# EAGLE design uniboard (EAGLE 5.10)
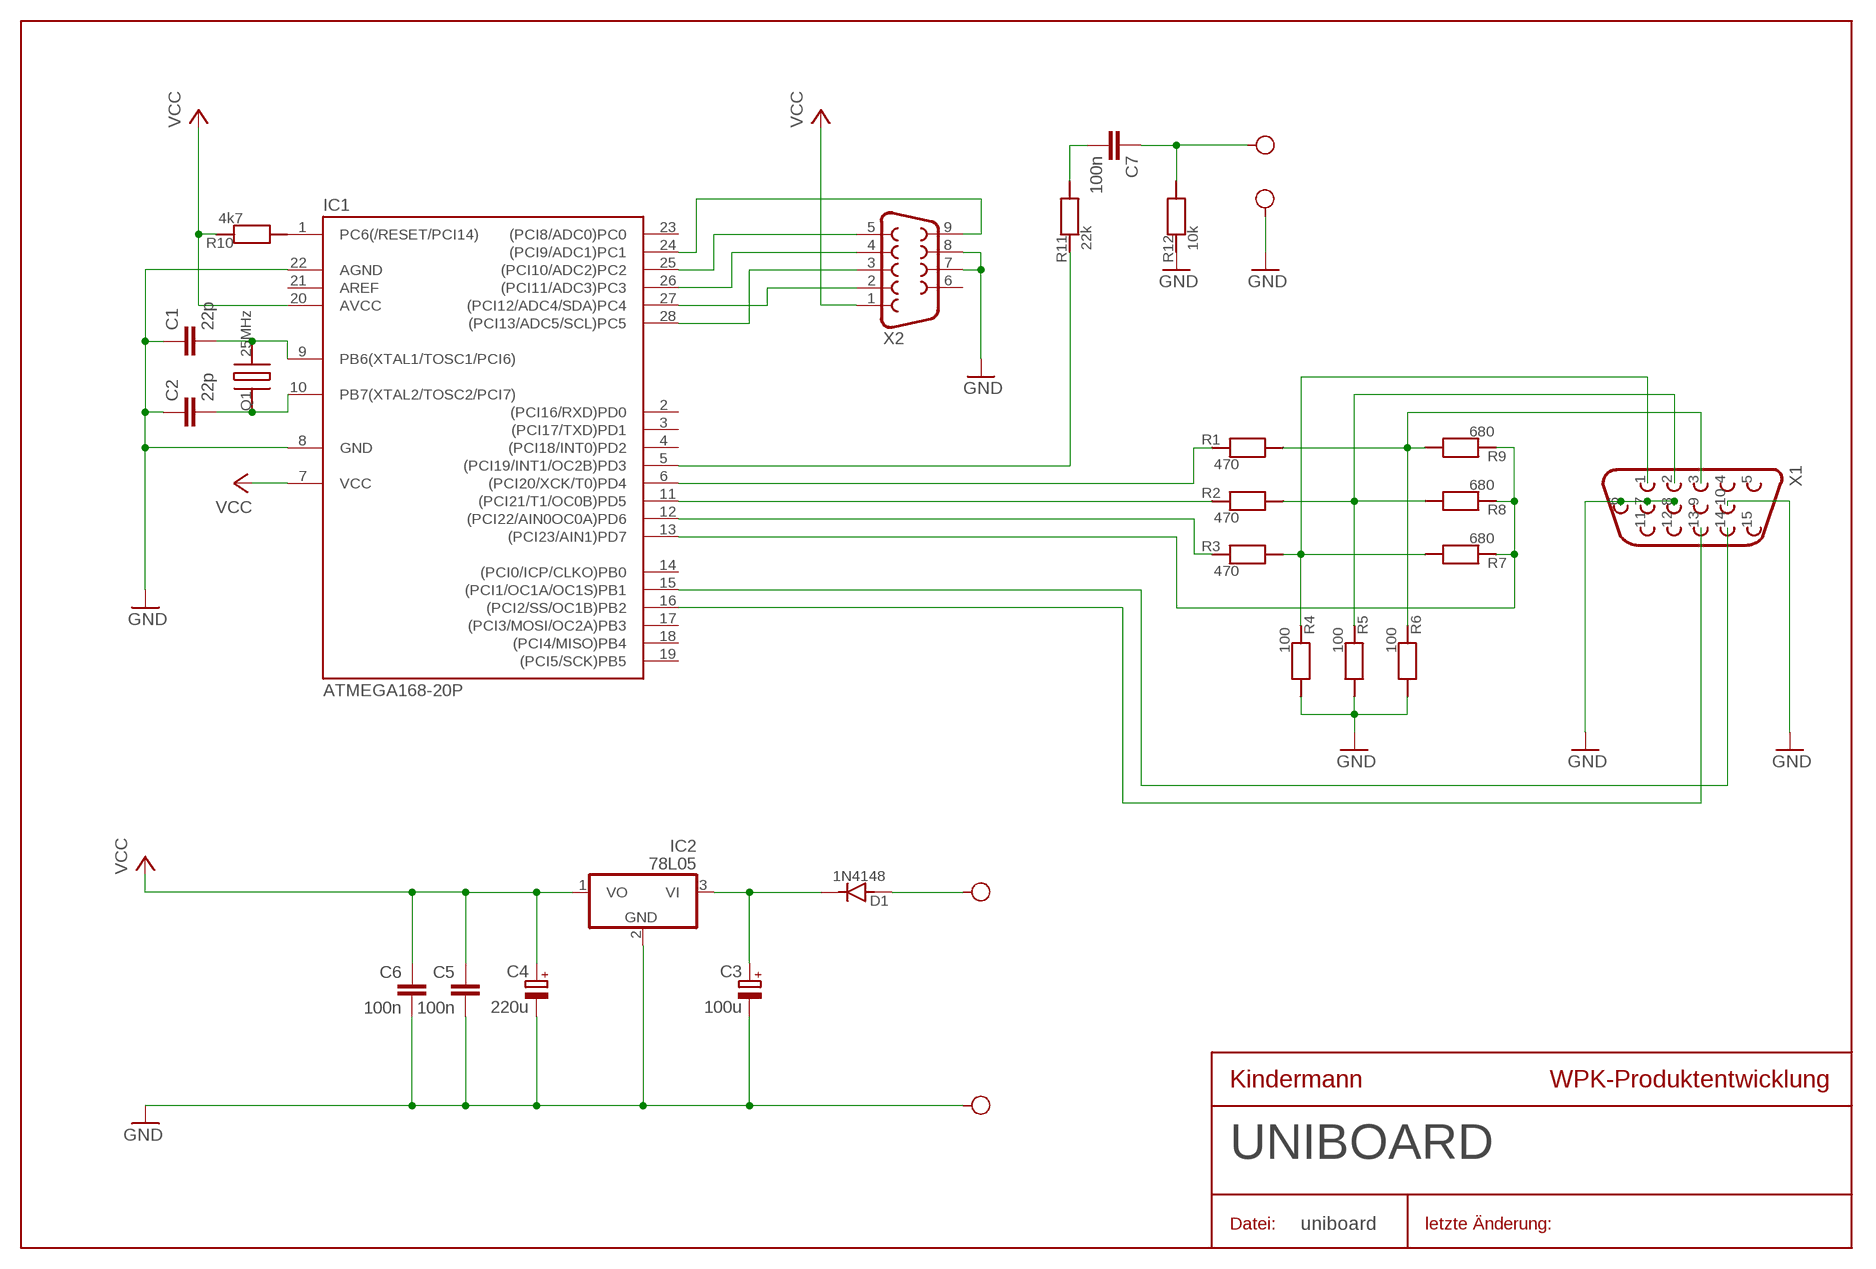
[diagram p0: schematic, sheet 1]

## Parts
C1  22p  KERKO-5.0  [KERKO-5.0]
C2  22p  KERKO-5.0  [KERKO-5.0]
C3  100u  ELKO-GR  [ELKO-GR-5.0]
C4  220u  ELKO-KL  [ELKO-KL-5.0]
C5  100n  VS-KERKO-5.0  [VS-KERKO-5.0]
C6  100n  VS-KERKO-5.0  [VS-KERKO-5.0]
C7  100n  VS-KERKO-5.0  [VS-KERKO-5.0]
D1  1N4148  [DIO-7.5]
GND  GND  [LOETN]
IC1  ATMEGA168-20P  ATMEGA-168  [DIL28-3]
IC2  78L05  [TO92]
Q1  25MHz  QUARZ  [QUARZ]
R1  470  WID-470  [WID-470]
R2  470  WID-470  [WID-470]
R3  470  WID-470  [WID-470]
R4  100  WID-100  [WID-100]
R5  100  WID-100  [WID-100]
R6  100  WID-100  [WID-100]
R7  680  WID-680  [WID-680]
R8  680  WID-680  [WID-680]
R9  680  WID-680  [WID-680]
R10  4k7  WID-4.7K  [WID-4.7K]
R11  22k  WID-22K  [WID-22K]
R12  10k  WID-10K  [WID-10K]
U$1  GND  [LOETN]
U$4  AUDIO  [LOETN]
VCC  VCC  [LOETN]
X1  VGA-BU-15POL  [VGA-BU-15POL]
X2  D-SUB-ST-9POL  [M09HP]

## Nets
B: R1.P2 R6.P1 R9.P2 X1.3
G: R2.P2 R5.P1 R8.P2 X1.2
GND: C1.1 C2.1 C3.- C4.- C5.2 C6.2 GND.PIN IC1.8(GND) IC1.22(AGND) IC2.2(GND) R4.P2 R5.P2 R6.P2 R12.1 U$1.PIN X1.6 X1.7 X1.8 X1.10 X2.7 X2.8
H/C-SYNC: IC1.16((PCI2/SS/OC1B)PB2) X1.13
N$1: C1.2 IC1.9(PB6(XTAL1/TOSC1/PCI6)) Q1.2
N$2: C7.1 R12.2 U$4.PIN
N$3: C2.2 IC1.10(PB7(XTAL2/TOSC2/PCI7)) Q1.1
N$4: IC1.11((PCI21/T1/OC0B)PD5) R2.P1
N$5: IC1.6((PCI20/XCK/T0)PD4) R1.P1
N$6: IC1.12((PCI22/AIN0OC0A)PD6) R3.P1
N$7: IC1.13((PCI23/AIN1)PD7) R7.P1 R8.P1 R9.P1
N$8: IC1.27((PCI12/ADC4/SDA)PC4) X2.2
N$12: IC1.24((PCI9/ADC1)PC1) X2.9
N$14: C7.2 R11.P2
N$17: IC1.5((PCI19/INT1/OC2B)PD3) R11.P1
N$21: IC1.28((PCI13/ADC5/SCL)PC5) X2.3
N$22: IC1.26((PCI11/ADC3)PC3) X2.4
N$27: IC1.25((PCI10/ADC2)PC2) X2.5
PIN: D1.A VCC.PIN
R: R3.P2 R4.P1 R7.P2 X1.1
RESET: IC1.1(PC6(/RESET/PCI14)) R10.P2
VCC: C4.+ C5.1 C6.1 IC1.7(VCC) IC1.20(AVCC) IC2.1(VO) R10.P1 X2.1
VIN3: C3.+ D1.K IC2.3(VI)
VSYNC: IC1.15((PCI1/OC1A/OC1S)PB1) X1.14
Unconnected: IC1.2((PCI16/RXD)PD0) IC1.3((PCI17/TXD)PD1) IC1.4((PCI18/INT0)PD2) IC1.14((PCI0/ICP/CLKO)PB0) IC1.17((PCI3/MOSI/OC2A)PB3) IC1.18((PCI4/MISO)PB4) IC1.19((PCI5/SCK)PB5) IC1.21(AREF) IC1.23((PCI8/ADC0)PC0) X1.4 X1.5 X1.9 X1.11 X1.12 X1.15 X2.6

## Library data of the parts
C1 C2 = pacman:KERKO-5.0: Keramik-Kondensator
C3 = pacman:ELKO-GR: Elektrolytkondensator, 10x12,5mm, RM 5,0mm
C4 = pacman:ELKO-KL: Elektrolytkondensator, 5x12,5mm, RM 5,0mm
C5-C7 = pacman:VS-KERKO-5.0: Vielschicht-Keramikkondensator
D1 = pacman:1N4148
GND U$1 = pacman:GND
IC1 = pacman:ATMEGA-168: Atmel AVR-RISC-Controller
IC2 = uniboard:78L05: Spannungsregler 0,1A positiv
Q1 = pacman:QUARZ: Quarz
R1-R3 = pacman:WID-470: Widertsand 470 Ohm
R4-R6 = pacman:WID-100: Widerstand 100 Ohm
R7-R9 = pacman:WID-680: Widerstand 680 Ohm
R10 = pacman:WID-4.7K: Widerstand 4.7K Ohm
R11 = pacman:WID-22K: Widerstand 22K Ohm
R12 = pacman:WID-10K: Widerstand 10K-Ohm
U$4 = pacman:AUDIO
VCC = pacman:VCC
X1 = uniboard:VGA-BU-15POL: VGA-Buchse 15pol
X2 = pacman:D-SUB-ST-9POL: D-SUB-Stecker, 9-polig, gewinkelt, RM 9,4

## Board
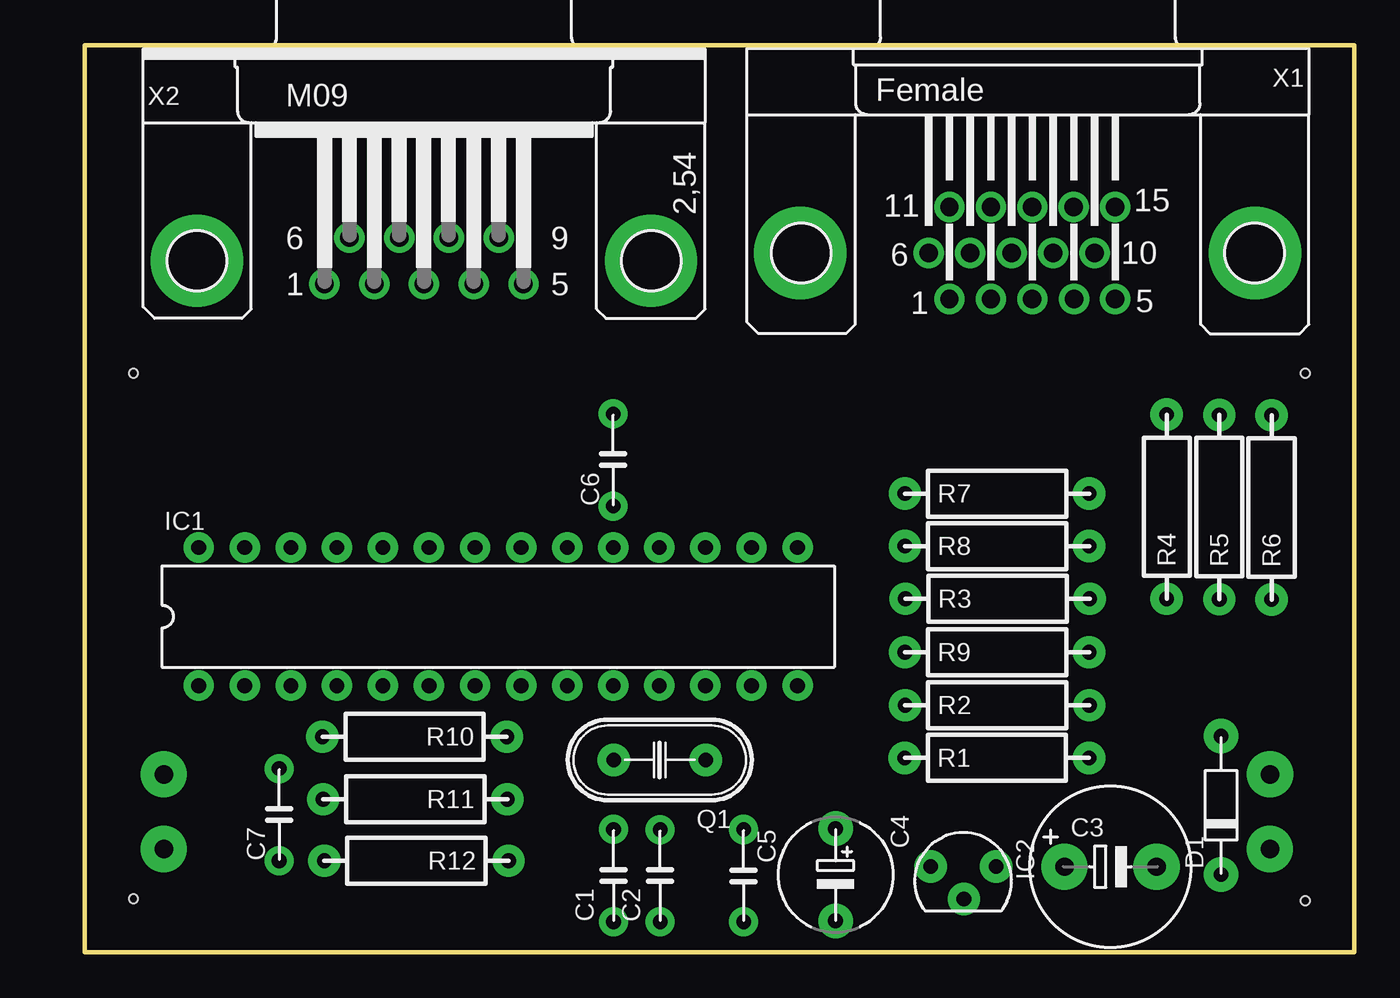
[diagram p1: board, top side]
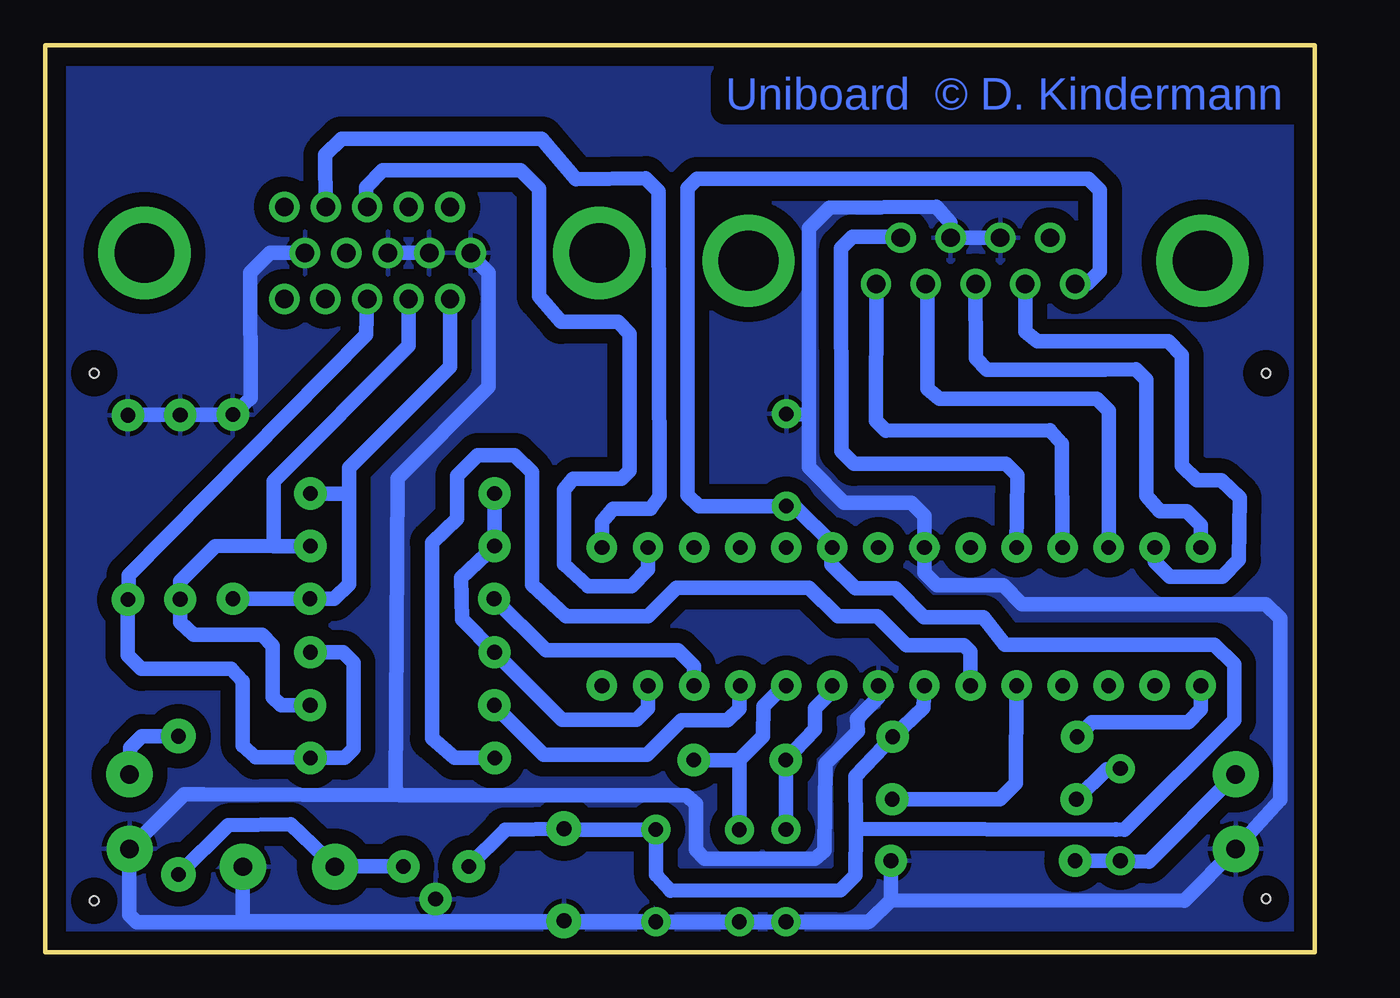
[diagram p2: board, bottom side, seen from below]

Size 70 x 50 mm. Coordinates in mm from the lower left corner, seen from the top.
Outline: 0,0 0,50 70,50 70,0 0,0
Copper layers (1*16): Top 0.035mm / dielectric 1.5mm / Bottom 0.035mm
Design rules "default": minimum track width 10mil, minimum drill 24mil, track to track 8mil, track to pad 8mil, pad to pad 8mil, via to via 8mil, smd to smd 8mil, copper to edge 40mil, drill to drill 8mil, minimum pad ring 10mil, minimum via ring 8mil, stop-mask expansion 4mil, vias tented up to drill 0mil, thermal gap 10mil
Holes 0.5 mm at 2.69,31.93 2.69,2.96 67.3,31.93 67.3,2.85

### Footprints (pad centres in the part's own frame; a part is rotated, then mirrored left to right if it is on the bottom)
KERKO-5.0 = drill 0.813 pad 1.6 round: 1 -2.54,0; 2 2.54,0
ELKO-GR-5.0 = drill 1.016 pad 2.54 round: + -2.54,0; - 2.54,0
ELKO-KL-5.0 = drill 0.813 pad 1.905 round: + -2.54,0; - 2.54,0
VS-KERKO-5.0 = drill 0.813 pad 1.6 round: 1 -2.54,0; 2 2.54,0
DIO-7.5 = drill 0.813 pad 1.905 round: A 3.81,0; K -3.81,0
LOETN = drill 1.016 pad 2.54 round: PIN 0,0
DIL28-3 = drill 0.813 pad 1.676 round: 1 -16.51,-3.81; 2 -13.97,-3.81; 3 -11.43,-3.81; 4 -8.89,-3.81; 5 -6.35,-3.81; 6 -3.81,-3.81; 7 -1.27,-3.81; 8 1.27,-3.81; 9 3.81,-3.81; 10 6.35,-3.81; 11 8.89,-3.81; 12 11.43,-3.81; 13 13.97,-3.81; 14 16.51,-3.81; 15 16.51,3.81; 16 13.97,3.81; 17 11.43,3.81; 18 8.89,3.81; 19 6.35,3.81; 20 3.81,3.81; 21 1.27,3.81; 22 -1.27,3.81; 23 -3.81,3.81; 24 -6.35,3.81; 25 -8.89,3.81; 26 -11.43,3.81; 27 -13.97,3.81; 28 -16.51,3.81
TO92 = drill 0.813 pad 1.778 round: 1 0,-1.795; 2 1.794,0.035; 3 0,1.812
QUARZ = drill 0.813 pad 1.778 round: 1 0,0; 2 5.08,0
WID-470 = drill 0.813 pad 1.778 round: P1 -5.08,0; P2 5.08,0
WID-100 = drill 0.813 pad 1.778 round: P1 -5.08,0; P2 5.08,0
WID-680 = drill 0.813 pad 1.778 round: P1 -5.08,0; P2 5.08,0
WID-4.7K = drill 0.813 pad 1.778 round: P1 -5.08,0; P2 5.08,0
WID-22K = drill 0.813 pad 1.778 round: P1 -5.08,0; P2 5.08,0
WID-10K = drill 0.813 pad 1.778 round: 1 -5.08,0; 2 5.08,0
VGA-BU-15POL = drill 1.016 pad 1.676 round: 1 4.329,2.54; 2 2.043,2.54; 3 -0.243,2.54; 4 -2.54,2.529; 5 -4.815,2.54; 6 5.472,0; 7 3.186,0; 8 0.9,0; 9 -1.386,0; 10 -3.672,0; 11 4.329,-2.54; 12 2.043,-2.54; 13 -0.243,-2.54; 14 -2.529,-2.54; 15 -4.815,-2.54 | drill 3.302 pad 5.08 round: G1 -12.522,0; G3 12.56,0
M09HP = drill 1.016 pad 1.676 round: 1 -5.486,-1.27; 2 -2.743,-1.27; 3 0,-1.27; 4 2.743,-1.27; 5 5.486,-1.27; 6 -4.115,1.27; 7 -1.372,1.27; 8 1.372,1.27; 9 4.115,1.27 | drill 3.302 pad 5.08 round: G1 -12.522,0; G2 12.522,0

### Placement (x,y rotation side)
C1  29.16,4.24 90 top
C2  31.73,4.23 90 top
C3  56.56,4.72 0 top
C4  41.4,4.28 270 top
C5  36.34,4.24 270 top
C6  29.14,27.15 90 top
C7  10.72,7.6 90 top
D1  62.66,8.11 90 top
GND  65.36,5.7 90 top
IC1  22.8,18.51 0 top
IC2  48.45,4.74 270 top
Q1  34.25,10.61 180 top
R1  50.3,10.72 0 top
R2  50.32,13.63 0 top
R3  50.34,19.49 0 top
R4  59.66,24.57 90 top
R5  62.56,24.55 90 top
R6  65.44,24.53 90 top
R7  50.31,25.29 0 top
R8  50.31,22.4 0 top
R9  50.31,16.55 0 top
R10  18.19,11.89 180 top
R11  18.23,8.44 180 top
R12  18.29,5.05 180 top
U$1  4.36,5.7 270 top
U$4  4.36,9.81 270 top
VCC  65.36,9.81 90 top
X1  52.01,38.56 180 top
X2  18.71,38.13 0 top

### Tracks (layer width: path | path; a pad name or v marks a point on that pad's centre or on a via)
B
  Bottom 0.813: R9.P2 53.58,16.55 53.01,15.98 53.01,11.22 53.51,10.72 R1.P2 55.41,10.75 58.41,10.75 59.11,11.4 59.11,14.94 59.75,15.63 64.7,15.63 65.46,16.38 65.45,19.49 65.4,19.49 | X1.3 52.31,34.04 65.4,20.79 65.4,19.49 | 65.4,19.49 R6.P1
G
  Bottom 0.406: 57.41,22.41 57.4,22.4
  Bottom 0.813: R2.P2 57.01,13.63 57.45,14.07 57.45,16.92 58.04,17.51 61.82,17.51 62.56,18.21 R5.P1 62.56,20.45 60.64,22.39 57.41,22.41 57.4,24.25 57.4,25.99 49.97,33.43 X1.2 | 57.4,22.4 R8.P2
GND
  Bottom 0.406: R12.1 23.64,5.05 23.64,5.11 23.43,5.11 23.43,2.63 23.7,2.63 24.68,1.66 | GND.PIN
  Bottom 0.813: X2.7 X2.8 20.08,40.23 20.86,41.09 26.76,41.04 27.89,39.92 27.89,29.63 | IC1.8 24.07,14.07 25.24,12.89 25.19,12.19 26.98,10.39 27.03,5.61 27.57,5.16 33.64,5.16 34.13,5.65 34.13,8.21 34.67,8.65 50.47,8.65 | 50.47,8.65 61.29,8.71 62.35,8.71 GND.PIN | X1.6 46.54,38.44 45.56,37.46 45.56,31.18 50.58,26.14 50.68,8.99 50.47,8.65 | R6.P2 65.42,29.63 R5.P2 61.26,29.63 R4.P2 58.68,30.55 58.7,37.46 57.61,38.55 X1.10 | 27.89,29.63 C6.2 | 27.89,29.63 27.89,26.73 25.95,24.8 22.25,24.8 21.52,24.07 IC1.22 21.53,20.93 20.83,20.23 17.16,20.23 16.14,19.21 2.7,19.21 1.91,18.41 1.9,8.42 U$1.PIN 7.19,2.86 23.38,2.87 | 23.38,2.87 R12.1 | 23.38,2.87 24.59,1.69 C1.1 C2.1 36.33,1.69 C5.2 36.47,1.7 36.47,1.73 C4.- 48.47,1.73 48.45,1.72 | IC2.2 48.47,2.94 48.45,1.72 | C3.- 59.13,4.72 59.11,1.72 48.45,1.72 | 24.68,1.66 64.96,1.66 65.37,2.06 GND.PIN | X1.7 X1.8
  pour Bottom (isolate 0.813): 69.9,0.1 69.83,50.11 -0.04,49.96 -0.07,0
H/C-SYNC
  Bottom 0.813: IC1.16 36.77,21.11 37.68,20.19 40.07,20.19 41.38,21.4 41.38,25.52 40.89,26.1 38.23,26.12 37.77,26.56 37.77,34.11 38.42,34.75 41.57,34.75 42.78,36.17 42.78,42.09 43.8,43.11 51.39,43.11 52.32,42.18 52.32,41.16 X1.13
N$1
  Bottom 0.813: C1.2 29.16,8.07 Q1.2 29.11,10.66 28.18,11.66 27.55,12.29 27.55,13.46 26.56,14.45 26.56,14.66 IC1.9
N$2
  Bottom 0.813: R12.2 C7.1 9.16,5 U$4.PIN
N$3
  Bottom 0.813: IC1.10 29.26,14.7 30.39,13.58 30.44,11.91 31.76,10.59 | 31.76,10.59 33.73,10.59 Q1.1 | C2.2 31.73,10.56 31.76,10.59
N$4
  Bottom 0.813: R2.P1 45.24,13.61 42.53,10.9 36.82,10.9 34.91,12.8 32.37,12.8 31.74,13.44 31.74,14.65 IC1.11
N$5
  Bottom 0.813: R1.P1 47.43,10.72 48.68,11.8 48.68,22.59 47.3,23.92 47.3,26.27 46.16,27.41 44.12,27.41 43.17,26.46 43.15,20.27 41.28,18.52 36.77,18.52 35.18,20.11 27.88,20.11 26.29,18.52 24.12,18.52 22.53,16.93 19.36,16.93 18.99,16.57 IC1.6
N$6
  Bottom 0.813: R3.P1 42.4,16.65 35.11,16.64 34.24,15.78 IC1.12
N$7
  Bottom 0.813: R7.P1 R8.P1 47.07,20.64 47.02,18.36 R9.P1 41.51,12.82 37.4,12.82 36.77,13.45 IC1.13
N$8
  Bottom 0.813: X2.2 15.96,34.22 15.31,33.7 8.08,33.7 7.33,32.91 7.33,26.82 6.49,26.02 5.17,26.02 4.14,25.06 4.18,21.63 5.11,20.71 7.98,20.71 8.82,21.54 8.82,22.32 IC1.27
N$12
  Bottom 0.813: IC1.24 16.4,26.31 17.03,26.93 25.43,26.93 26.1,27.63 26.13,38.83 25.5,39.46 22.89,39.46 X2.9
N$14
  Bottom 0.813: R11.P2 11.47,10.11 C7.2
N$17
  Bottom 0.813: IC1.5 16.47,9.32 17.35,8.44 R11.P1
N$21
  Bottom 0.813: X2.3 18.7,32.76 18.09,32.13 11.58,32.13 9.87,32.15 9.28,31.56 9.28,25.16 8.54,24.32 7.06,24.32 6.29,23.55 IC1.28
N$22
  Bottom 0.813: IC1.26 11.37,29.85 12.02,30.51 20.71,30.51 21.36,31.07 21.36,36.77 X2.4
N$27
  Bottom 0.813: IC1.25 13.95,28.05 14.6,28.77 23.66,28.75 24.19,29.32 24.18,36.5 X2.5
PIN
  Bottom 0.813: VCC.PIN 65.33,11.27 64.68,11.92 D1.A
R
  Bottom 0.813: R4.P1 R3.P2 54.08,19.49 53.26,20.31 53.26,24.97 | 53.26,24.97 53.26,25.13 53.43,25.29 R7.P2 | X1.1 47.68,32.28 53.26,26.73 53.26,25.16 53.26,24.97
RESET
  Bottom 0.813: IC1.1 6.29,13.4 6.99,12.7 12.3,12.7 R10.P2
VCC
  Bottom 0.813: IC1.7 21.57,13.49 R10.P1 25.32,9.7 25.31,6.83 | 25.31,6.83 10.98,6.77 10.98,6.8 10.5,6.76 4.45,12.8 4.45,14.12 4.45,15.88 5.54,16.96 17.08,16.96 18.28,18.49 21.54,18.49 23.12,20.06 25.34,20.06 26.66,21.38 26.66,22.27 IC1.20 26.62,22.56 28.63,24.55 29.14,24.55 C6.1 33.95,24.6 34.59,25.21 34.58,42.12 34.06,42.63 12.47,42.63 11.84,42 11.84,37.55 12.54,36.86 X2.1 | 25.31,6.83 25.33,4.25 26.16,3.41 35.52,3.4 36.31,4.26 36.32,4.27 36.32,6.76 C5.1 42.14,6.78 C4.+ 44.66,6.78 44.66,6.73 IC2.1
VIN3
  Bottom 0.813: C3.+ 54.3,4.96 | C3.+ 54.33,4.74 | D1.K 59.91,7.01 56.47,7.05 C3.+ | IC2.3 54.02,4.74 C3.+
VSYNC
  Bottom 0.813: IC1.15 39.31,23.73 38.7,24.47 36.64,24.47 36.14,25.15 36.19,41.97 36.9,42.68 40.73,42.63 42.64,44.86 53.66,44.86 54.56,43.96 X1.14

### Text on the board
Bottom: Uniboard © D. Kindermann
